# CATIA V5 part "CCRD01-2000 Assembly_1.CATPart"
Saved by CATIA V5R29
Part number: CCRD01-2000 Assembly_1
Definition: design
Source: Unknown
Bounding box of the stored display mesh (mm): x -250 to 250, y 0 to 0, z -1000 to 1000
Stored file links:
  C:\가치같이\SmartFactory_BoxErectorConveyor\CCRD01-2000 Assembly_1.CATPart
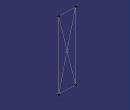
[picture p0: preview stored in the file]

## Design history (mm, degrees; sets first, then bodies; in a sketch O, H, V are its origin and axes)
Set1
  Point1 to Point6 "Sketch2": stored without definition
  Line1 "LINE #661795": stored without definition
  DatumCurve1 "Sketch2"
  Line2 "LINE #661813": stored without definition
  Line3 "LINE #661818": stored without definition
  Line4 "LINE #661823": stored without definition
Body1 (main body)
